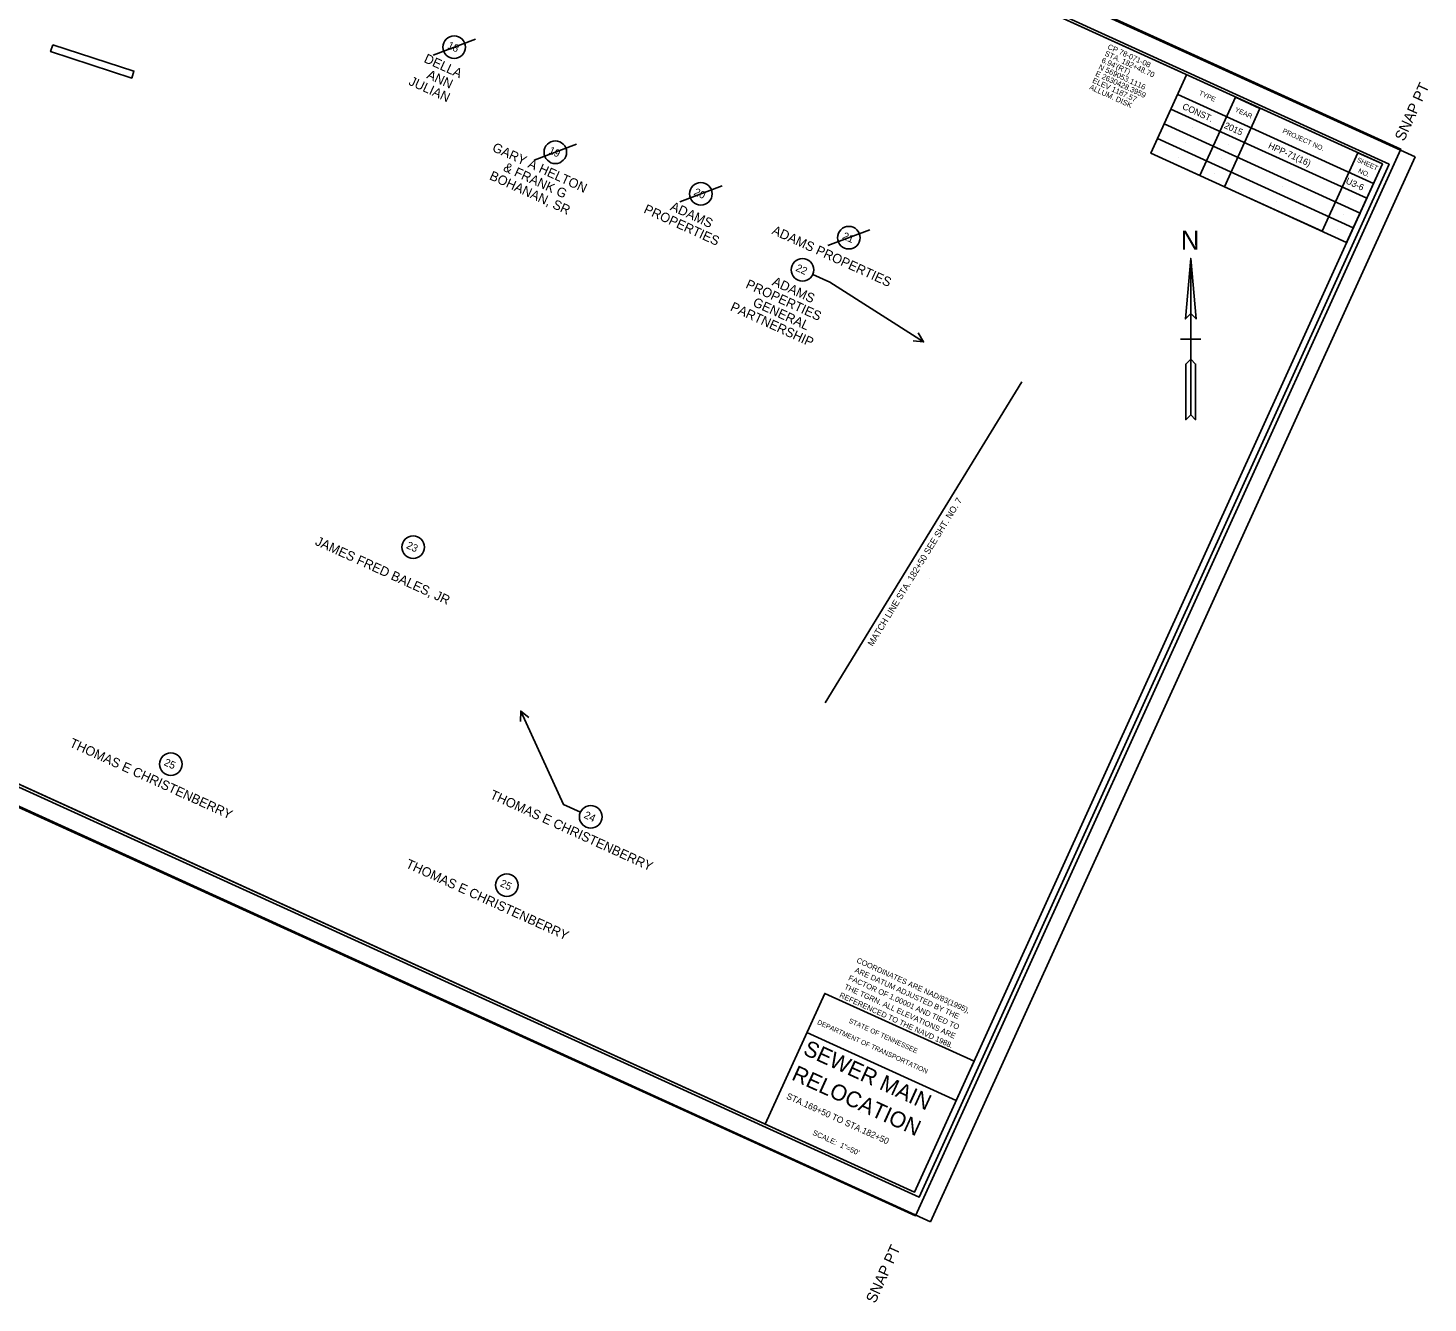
# Model space of a CAD drawing. Extents: x 2628810 to 2630911, y 568379 to 570218.
# Drawn here: x 2629609 to 2630911, y 568379 to 569564 of the extents above; entities that cross this region are included whole.
import ezdxf

# ---------------------------------------------------------------- set-up
doc = ezdxf.new("R2010")
doc.units = 0
for name, color, linetype in [('DESIGN - CENTERLINE - Proposed Text', 7, 'Continuous'), ('DESIGN - SCRATCH - User 1', 7, 'Continuous'), ('DESIGN - SHEET - Corner Text', 7, 'Continuous'), ('DESIGN - SHEET - Light Grid', 7, 'Continuous'), ('DESIGN - SHEET - Linework', 7, 'Continuous'), ('DESIGN - SHEET - Plot Shape', 7, 'Continuous'), ('SURVEY - CONTROL with Text', 7, 'Continuous'), ('SURVEY - GROUND - Top of Ground', 7, 'Continuous'), ('SURVEY - PROPERTY - Owners', 7, 'Continuous'), ('SURVEY - PROPERTY - Tract Numbers', 7, 'Continuous')]:
    doc.layers.add(name, color=color, linetype=linetype)

msp = doc.modelspace()

# ---------------------------------------------------------------- linework, layer by layer
at = {"layer": 'DESIGN - CENTERLINE - Proposed Text'}
for p, q in [((2630689.9, 569274.6), (2630680.4, 569274.6)), ((2630699.3, 569274.6), (2630689.9, 569274.6))]:
    msp.add_line(p, q, dxfattribs=at)
for points in [[(2630689.9, 569349.6), (2630685, 569293.3), (2630689.9, 569298.2), (2630694.8, 569293.3), (2630689.9, 569349.6), (2630689.9, 569204.2), (2630694.4, 569199.6), (2630694.4, 569251.4), (2630689.9, 569255.9), (2630685.3, 569251.4), (2630685.3, 569199.6), (2630689.9, 569204.2)], [(2630349.9, 568936.6), (2630441.4, 569085.8), (2630532.9, 569234.9)]]:
    msp.add_lwpolyline(points, dxfattribs=at)
for points in [[(2630689.9, 569298.2), (2630694.8, 569293.3), (2630689.9, 569349.6)], [(2630685.3, 569199.6), (2630689.9, 569204.2), (2630689.9, 569255.9), (2630685.3, 569251.4)]]:
    msp.add_lwpolyline(points, close=True, dxfattribs=at)
at = {"layer": 'DESIGN - SCRATCH - User 1'}
for p, q in [((2630697.4, 569484.7), (2630697.4, 569484.7)), ((2630691.2, 569471.1), (2630691.2, 569471.1)), ((2630731.1, 569469.4), (2630731.1, 569469.4)), ((2630685, 569457.4), (2630685, 569457.4)), ((2630724.9, 569455.7), (2630724.9, 569455.7)), ((2630678.8, 569443.8), (2630678.8, 569443.8)), ((2630718.7, 569442.1), (2630718.7, 569442.1)), ((2630788, 569443.5), (2630788, 569443.5)), ((2630712.4, 569428.4), (2630712.4, 569428.4)), ((2630781.7, 569429.9), (2630781.7, 569429.9)), ((2630775.5, 569416.2), (2630775.5, 569416.2)), ((2630844.8, 569417.6), (2630844.8, 569417.6)), ((2630769.3, 569402.6), (2630769.3, 569402.6)), ((2630838.6, 569404), (2630838.6, 569404)), ((2630832.4, 569390.3), (2630832.4, 569390.3)), ((2630826.2, 569376.7), (2630826.2, 569376.7)), ((2630446.5, 569052.3), (2630446.5, 569052.3)), ((2630383, 568555.8), (2630383, 568555.8))]:
    msp.add_line(p, q, dxfattribs=at)
at = {"layer": 'DESIGN - SHEET - Light Grid'}
msp.add_lwpolyline([(2628921.9, 569166.8), (2630437.2, 568477), (2630874.3, 569437.1), (2629359, 570127)], close=True, dxfattribs=at)
at = {"layer": 'DESIGN - SHEET - Linework'}
for p, q in [((2629260.3, 570189.7), (2630898.6, 569443.9)), ((2630898.6, 569443.9), (2630448, 568454.2)), ((2628809.8, 569200), (2630448, 568454.2))]:
    msp.add_line(p, q, dxfattribs=at)
for points in [[(2629435.3, 570089.5), (2629000.3, 569133.8), (2630433, 568481.6), (2630868.1, 569437.3), (2629435.3, 570089.5)], [(2630686, 569520.1), (2630652.9, 569447.3), (2630834.9, 569364.4), (2630868.1, 569437.3), (2630845.3, 569447.6), (2630812.2, 569374.8), (2630721.2, 569416.2), (2630754.3, 569489), (2630731.6, 569499.4), (2630698.4, 569426.6), (2630652.9, 569447.3), (2630659.1, 569461), (2630841.1, 569378.1), (2630847.4, 569391.7), (2630665.3, 569474.6), (2630671.5, 569488.3), (2630853.6, 569405.4), (2630859.8, 569419.1), (2630677.8, 569501.9)], [(2630294.2, 568544.8), (2630349.6, 568666.4), (2630488.4, 568603.3), (2630471.8, 568566.9), (2630333, 568630)]]:
    msp.add_lwpolyline(points, dxfattribs=at)
at = {"layer": 'DESIGN - SHEET - Plot Shape'}
for points in [[(2629338, 570155.5), (2630885.2, 569451.1), (2630433.8, 568459.6), (2628886.6, 569164)], [(2629357.9, 570124.7), (2630868.1, 569437.3), (2630433, 568481.6), (2628922.9, 569169.1)]]:
    msp.add_lwpolyline(points, close=True, dxfattribs=at)
at = {"layer": 'SURVEY - GROUND - Top of Ground'}
msp.add_lwpolyline([(2629631.7, 569548.2), (2629629.6, 569541.8), (2629705.1, 569517.2), (2629707.1, 569523.6)], close=True, dxfattribs=at)
at = {"layer": 'SURVEY - PROPERTY - Tract Numbers'}
for p, q in [((2629985.3, 569538.5), (2630024.6, 569553.3)), ((2630079.4, 569440.9), (2630118.7, 569455.6)), ((2630214.7, 569402.1), (2630254, 569416.9)), ((2630352.3, 569361.4), (2630391.6, 569376.2))]:
    msp.add_line(p, q, dxfattribs=at)
for points in [[(2630354.3, 569327.4), (2630338.4, 569334.7)], [(2630441.4, 569272), (2630354.3, 569327.4)], [(2630436.4, 569280.4), (2630441.4, 569272), (2630431.7, 569273)], [(2630074.5, 568922.7), (2630066.9, 568928.8), (2630066.5, 568919.1)], [(2630066.9, 568928.8), (2630106.5, 568842.1), (2630122.4, 568834.9)]]:
    msp.add_lwpolyline(points, dxfattribs=at)
for centre in [(2630005, 569545.9), (2630099, 569448.2), (2630234.4, 569409.5), (2630372, 569368.8), (2630328.8, 569339), (2629966.7, 569081.2), (2629741.4, 568879.5), (2630131.9, 568830.5), (2630053.9, 568767)]:
    msp.add_circle(centre, 10.5, dxfattribs=at)

# ---------------------------------------------------------------- texts
at = {"layer": 'DESIGN - CENTERLINE - Proposed Text'}
msp.add_text('N', height=17.7, dxfattribs=at).set_placement((2630680.8, 569357.7))
msp.add_text('MATCH LINE STA. 182+50 SEE SHT. NO. 7', height=6, rotation=58.4832, dxfattribs=at).set_placement((2630394.1, 568988.5))
at = {"layer": 'DESIGN - SHEET - Corner Text'}
for s, height, rotation, p in [('TYPE', 4.5, 335.5232, (2630697.1, 569501.7)), ('  SNAP PT', 10, 65.5232, (2630885.2, 569451.1)), ('CONST.', 6, 335.5232, (2630681.5, 569488.7)), ('YEAR', 4.5, 335.5232, (2630730.5, 569486.3)), ('2015', 6, 335.5232, (2630720.4, 569471)), ('PROJECT NO.', 4.5, 335.5232, (2630774.8, 569466.5)), ('HPP-71(16)', 6, 335.5232, (2630761.4, 569452.3)), ('SHEET', 4.5, 335.5232, (2630844, 569439.6)), ('NO.', 4.5, 335.5232, (2630845.1, 569429.5)), ('U3-6', 6, 335.5232, (2630833.5, 569419.5)), ('COORDINATES ARE NAD/83(1995),', 5, 335.5232, (2630378.6, 568695.4)), ('FACTOR OF 1.00001 AND TIED TO', 5, 335.5232, (2630371, 568679.1)), ('ARE DATUM ADJUSTED BY THE', 5, 335.5232, (2630376.9, 568686.3)), ('THE TGRN. ALL ELEVATIONS ARE', 5, 335.5232, (2630367.2, 568670.9)), ('REFERENCED TO THE NAVD 1988.', 5, 335.5232, (2630362.7, 568663)), ('DEPARTMENT OF TRANSPORTATION', 4.5, 335.5232, (2630342.1, 568638.1)), ('STATE OF TENNESSEE', 4.5, 335.5232, (2630371.4, 568639.4)), ('SEWER MAIN', 14.76, 335.5232, (2630328.5, 568610.1)), ('RELOCATION', 14.76, 335.5232, (2630317.8, 568586.6)), ('STA.169+50 TO STA.182+50', 5.906, 335.5232, (2630313.3, 568568.8)), ('SCALE:  1"=50\'', 4.922, 335.5232, (2630337.7, 568535.2)), ('SNAP PT  ', 10, 65.5232, (2630396.5, 568377.7))]:
    msp.add_text(s, height=height, rotation=rotation, dxfattribs=at).set_placement(p)
at = {"layer": 'SURVEY - CONTROL with Text'}
for s, p in [('STA. 182+48.70', (2630609.3, 569538.3)), ('CP 78-071-08', (2630612.1, 569544.5)), ('N 569053.1116', (2630603.6, 569525.7)), ("6.94'(RT)", (2630606.4, 569532)), ('ELEV 1187.57', (2630597.9, 569513.2)), ('E 2630428.3959', (2630600.7, 569519.5)), ('ALLUM. DISK', (2630595, 569507))]:
    msp.add_text(s, height=5, rotation=335.5232, dxfattribs=at).set_placement(p)
at = {"layer": 'SURVEY - PROPERTY - Owners'}
for s, p in [('DELLA', (2629976.1, 569532.2)), ('JULIAN', (2629961.9, 569511.2)), ('ANN', (2629978.7, 569517.3)), ('GARY A HELTON', (2630039.6, 569449.6)), ('& FRANK G', (2630049.9, 569431.2)), ('BOHANAN, SR', (2630037, 569423.3)), ('PROPERTIES', (2630180.5, 569392.3)), ('ADAMS', (2630205.1, 569394.8)), ('ADAMS PROPERTIES', (2630299.6, 569372.6)), ('PROPERTIES', (2630275.3, 569322.5)), ('ADAMS', (2630299.9, 569325)), ('PARTNERSHIP', (2630261, 569301.5)), ('GENERAL', (2630281.9, 569305.7)), ('JAMES FRED BALES, JR', (2629874.9, 569083.6)), ('THOMAS E CHRISTENBERRY', (2629646.5, 568896.1)), ('THOMAS E CHRISTENBERRY', (2630037.5, 568848)), ('THOMAS E CHRISTENBERRY', (2629959.2, 568783.7))]:
    msp.add_text(s, height=8.75, rotation=335.5232, dxfattribs=at).set_placement(p)
at = {"layer": 'SURVEY - PROPERTY - Tract Numbers'}
for s, p in [('18', (2629998, 569545.2)), ('19', (2630092.1, 569447.5)), ('20', (2630227.2, 569408.9)), ('21', (2630365.3, 569368)), ('22', (2630321.9, 569338.3)), ('23', (2629959.8, 569080.5)), ('25', (2629734.4, 568878.8)), ('24', (2630125, 568829.8)), ('25', (2630047, 568766.3))]:
    msp.add_text(s, height=7, rotation=335.5232, dxfattribs=at).set_placement(p)

doc.saveas('drawing.dxf')
